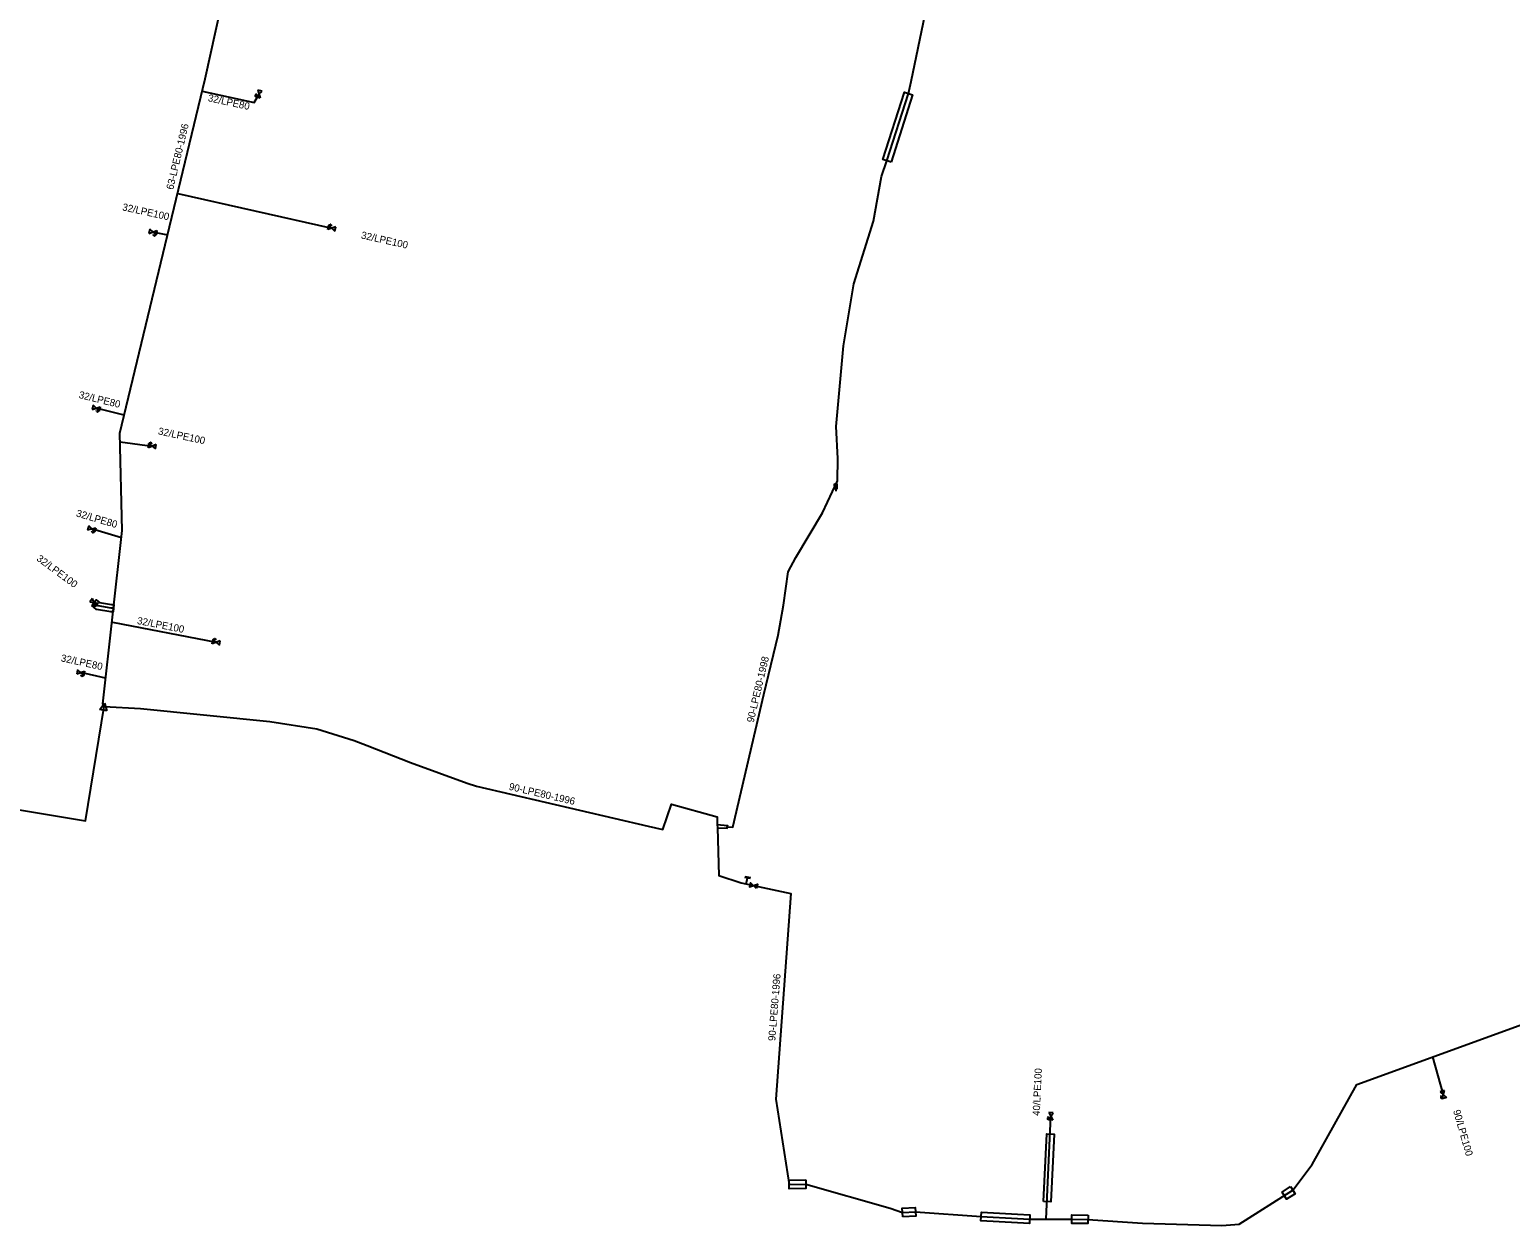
# Model space of a CAD drawing. Extents: x -741323 to -735641, y -1146295 to -1143223.
# Drawn here: x -736387.1 to -736181.6, y -1145177.5 to -1145011.4 of the extents above; entities that cross this region are included whole.
import ezdxf

# ---------------------------------------------------------------- set-up
doc = ezdxf.new("R2010")
doc.units = 0
for name, color, linetype in [('Vrstva 1', 7, 'Continuous'), ('Vrstva 21', 7, 'Continuous'), ('Vrstva 22', 7, 'Continuous'), ('Vrstva 24', 7, 'Continuous'), ('Vrstva 26', 7, 'Continuous'), ('Vrstva 29', 7, 'Continuous'), ('Vrstva 31', 7, 'Continuous'), ('Vrstva 32', 7, 'Continuous')]:
    doc.layers.add(name, color=color, linetype=linetype)

# ---------------------------------------------------------------- blocks, each defined once
blk = doc.blocks.new('DEC128')
at = {"layer": 'Vrstva 1'}
for p, q in [((-0.4, 1), (0.4, 1)), ((-0.4, 0.9), (0.4, 0.9)), ((0, 0), (0, 0.9))]:
    blk.add_line(p, q, dxfattribs=at)
blk = doc.blocks.new('DEC122')
at = {"layer": 'Vrstva 1'}
for p, q in [((-0.5, 0.5), (0.5, 0)), ((-0.5, -0.5), (-0.5, 0.5)), ((0.5, 0), (-0.5, -0.5))]:
    blk.add_line(p, q, dxfattribs=at)
blk = doc.blocks.new('DEC063-SN')
at = {"layer": 'Vrstva 1'}
for p, q in [((-0.5, -0.3), (0.5, 0.3)), ((0.5, -0.3), (-0.5, 0.3)), ((-0.5, 0.3), (-0.5, -0.3)), ((0.5, 0.3), (0.5, -0.3)), ((0.126, -0.318), (0.126, -0.458)), ((0.126, -0.384), (0.206, -0.384)), ((0.206, -0.458), (0.206, -0.318)), ((0.366, -0.458), (0.366, -0.318))]:
    blk.add_line(p, q, dxfattribs=at)
for points in [[(0.246, -0.318), (0.246, -0.418), (0.252, -0.438), (0.264, -0.451), (0.281, -0.458), (0.292, -0.458), (0.309, -0.451), (0.321, -0.438), (0.326, -0.418), (0.326, -0.318)], [(0.366, -0.318), (0.418, -0.318), (0.435, -0.325), (0.441, -0.331), (0.446, -0.344), (0.446, -0.364), (0.441, -0.378), (0.435, -0.384), (0.418, -0.391), (0.366, -0.391)]]:
    blk.add_lwpolyline(points, dxfattribs=at)
blk = doc.blocks.new('DEC129')
at = {"layer": 'Vrstva 1'}
blk.add_line((0, 1), (0, 0), dxfattribs=at)
blk.add_lwpolyline([(-0.15, 1), (0.15, 1), (0.15, 0.3), (-0.15, 0.3), (-0.15, 1)], dxfattribs=at)
blk = doc.blocks.new('DEC124')
at = {"layer": 'Vrstva 1'}
blk.add_lwpolyline([(-0.5, 0.3), (0.5, -0.3), (0.5, 0.3), (-0.5, -0.3), (-0.5, 0.3)], dxfattribs=at)

msp = doc.modelspace()

# ---------------------------------------------------------------- linework, layer by layer
at = {"layer": 'Vrstva 21'}
for points in [[(-736362.77, -1145018.28), (-736359, -1145001.23), (-736358.76, -1145000), (-736356.49, -1144988.39), (-736355.9, -1144986.98), (-736347.39, -1144988.9), (-736341.7, -1144990.24), (-736338.26, -1144991.32)], [(-736290.29, -1145122.15), (-736289.5, -1145122.18), (-736285.2, -1145103.78), (-736283.21, -1145095.54), (-736282.48, -1145091.38), (-736281.85, -1145086.73), (-736280.79, -1145084.74), (-736277.09, -1145078.52), (-736275.01, -1145074.12), (-736274.93, -1145071), (-736275.19, -1145066.54), (-736274.14, -1145055.37), (-736272.7, -1145046.74), (-736269.99, -1145038.04), (-736268.87, -1145031.83), (-736268.12, -1145029.66), (-736265.13, -1145020.32), (-736264.78, -1145018.64), (-736262.07, -1145005.67)], [(-736376.8, -1145105.45), (-736376.98, -1145105.04), (-736374.26, -1145080.99), (-736374.6, -1145067.5), (-736368.3, -1145041.31), (-736362.77, -1145018.28)], [(-736406.02, -1145118.75), (-736405.83, -1145116.93), (-736379.36, -1145121.32), (-736376.8, -1145105.45)], [(-736376.8, -1145105.45), (-736371.73, -1145105.7), (-736353.79, -1145107.52), (-736347.27, -1145108.55), (-736342.09, -1145110.15), (-736340.27, -1145110.85), (-736334.25, -1145113.21), (-736326.37, -1145116.08), (-736325.12, -1145116.49), (-736301.27, -1145122.06), (-736299.22, -1145122.49), (-736298.03, -1145119.01), (-736291.69, -1145120.73), (-736291.67, -1145121.81)], [(-736291.67, -1145121.81), (-736291.66, -1145122.29)], [(-736291.67, -1145121.81), (-736290.28, -1145121.94), (-736290.29, -1145122.15)], [(-736291.66, -1145122.29), (-736290.3, -1145122.34), (-736290.29, -1145122.15)], [(-736291.66, -1145122.29), (-736291.45, -1145128.91), (-736288.35, -1145129.93), (-736286.66, -1145130.3)], [(-736286.66, -1145130.3), (-736281.49, -1145131.39), (-736283.55, -1145159.93), (-736281.7, -1145171.8), (-736279.39, -1145171.75), (-736267.7, -1145175.09), (-736265.98, -1145175.71), (-736264.17, -1145175.59), (-736255.05, -1145176.24), (-736250, -1145176.51), (-736248.33, -1145176.6), (-736242.48, -1145176.62), (-736240.22, -1145176.64), (-736232.66, -1145177.17), (-736221.66, -1145177.48), (-736219.24, -1145177.33), (-736211.79, -1145172.61), (-736209.1, -1145169.02), (-736202.89, -1145157.91), (-736178.33, -1145148.97)]]:
    msp.add_lwpolyline(points, dxfattribs=at)
at = {"layer": 'Vrstva 29'}
for points in [[(-736267.55, -1145029.84), (-736268.7, -1145029.47), (-736265.7, -1145020.14), (-736264.56, -1145020.5)], [(-736378.5, -1145091.4), (-736377.88, -1145090.62), (-736377.41, -1145091), (-736375.74, -1145091.27), (-736375.45, -1145091.29), (-736375.52, -1145092.29), (-736375.86, -1145092.27), (-736377.83, -1145091.94)], [(-736246.4, -1145174.17), (-736245.93, -1145164.77), (-736244.93, -1145164.82), (-736245.4, -1145174.22)], [(-736279.4, -1145171.15), (-736279.38, -1145172.35), (-736281.69, -1145172.4), (-736281.71, -1145171.2)], [(-736212.11, -1145172.1), (-736211.47, -1145173.12), (-736212.65, -1145173.86), (-736213.29, -1145172.85)], [(-736265.94, -1145176.31), (-736266.02, -1145175.11), (-736264.21, -1145174.99), (-736264.13, -1145176.19)], [(-736250, -1145177.11), (-736255.08, -1145176.84), (-736255.02, -1145175.64), (-736250, -1145175.91), (-736248.3, -1145176), (-736248.36, -1145177.2)], [(-736240.21, -1145176.04), (-736240.22, -1145177.24), (-736242.48, -1145177.22), (-736242.47, -1145176.02)]]:
    msp.add_lwpolyline(points, close=True, dxfattribs=at)
at = {"layer": 'Vrstva 31'}
for points in [[(-736363.19, -1145020.01), (-736355.97, -1145021.57), (-736355.28, -1145020.4)], [(-736366.57, -1145034.21), (-736345.18, -1145039.01)], [(-736367.95, -1145039.98), (-736370.01, -1145039.56)], [(-736373.99, -1145064.96), (-736377.9, -1145064)], [(-736374.58, -1145068.66), (-736370.11, -1145069.28)], [(-736374.37, -1145081.99), (-736378.52, -1145080.77)], [(-736375.48, -1145091.79), (-736375.8, -1145091.77), (-736377.62, -1145091.47), (-736378.19, -1145091.01)], [(-736375.64, -1145093.73), (-736361.22, -1145096.52)], [(-736376.58, -1145101.49), (-736380.04, -1145100.73)], [(-736192.41, -1145154.09), (-736190.9, -1145159.33)], [(-736246.03, -1145176.57), (-736245.37, -1145162.34)]]:
    msp.add_lwpolyline(points, dxfattribs=at)

# ---------------------------------------------------------------- block references
at = {"layer": 'Vrstva 22', "rotation": 168.09458610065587}
msp.add_blockref('DEC124', (-736286.66, -1145130.3), dxfattribs=at)
at = {"layer": 'Vrstva 24'}
for name, p, rotation in [('DEC129', (-736275.23, -1145075.51), 0.2359722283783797), ('DEC128', (-736287.68, -1145130.08), -12.34919727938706)]:
    msp.add_blockref(name, p, dxfattribs=dict(at, rotation=rotation))
at = {"layer": 'Vrstva 26', "rotation": 80.8365166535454}
msp.add_blockref('DEC122', (-736376.8, -1145105.45), dxfattribs=at)
at = {"layer": 'Vrstva 32'}
for p, rotation in [((-736355.28, -1145020.4), -105.79371670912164), ((-736345.18, -1145039.01), 167.3393771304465), ((-736370.01, -1145039.56), -10.856413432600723), ((-736377.9, -1145064), -12.85592296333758), ((-736370.11, -1145069.28), 172.06724167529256), ((-736378.52, -1145080.77), -16.37816984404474), ((-736378.19, -1145091.01), -40.266542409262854), ((-736361.22, -1145096.52), 169.04593739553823), ((-736380.04, -1145100.73), -12.562297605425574), ((-736190.9, -1145159.33), -73.94680262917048), ((-736245.37, -1145162.34), -92.66300072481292)]:
    msp.add_blockref('DEC063-SN', p, dxfattribs=dict(at, rotation=rotation))

# ---------------------------------------------------------------- texts
at = {"layer": 'Vrstva 21'}
for s, rotation, p in [('63-LPE80-1996', 76.498, (-736367.21, -1145033.74)), ('90-LPE80-1998', 76.729, (-736286.64, -1145107.73)), ('90-LPE80-1996', 346.855, (-736320.67, -1145116.98)), ('90-LPE80-1996', 85.398, (-736283.63, -1145151.91))]:
    msp.add_text(s, height=1, rotation=rotation, dxfattribs=at).set_placement(p)
at = {"layer": 'Vrstva 31'}
for s, rotation, p in [('32/LPE80', 347.792, (-736362.44, -1145021.37)), ('32/LPE100', 347.701, (-736374.33, -1145036.52)), ('32/LPE100', 347.339, (-736341.19, -1145040.42)), ('32/LPE80', 346.156, (-736380.37, -1145062.58)), ('32/LPE100', 347.921, (-736369.35, -1145067.64)), ('32/LPE80', 343.622, (-736380.75, -1145079.01)), ('32/LPE100', 323.462, (-736386.25, -1145085.08)), ('32/LPE100', 349.046, (-736372.27, -1145093.96)), ('32/LPE80', 347.684, (-736382.85, -1145099.14)), ('40/LPE100', 87.337, (-736246.92, -1145162.29)), ('90/LPE100', 286.053, (-736189.55, -1145161.58))]:
    msp.add_text(s, height=1, rotation=rotation, dxfattribs=at).set_placement(p)

doc.saveas('drawing.dxf')
